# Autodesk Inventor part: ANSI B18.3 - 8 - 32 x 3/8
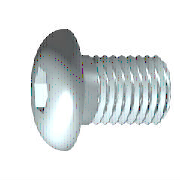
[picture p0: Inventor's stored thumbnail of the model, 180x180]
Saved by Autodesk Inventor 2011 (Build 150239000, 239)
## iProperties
IsCustomPart: 0
Created: 2008-02
Part Number: ANSI B18.3 - 8 - 32 x 3/8
Material: Steel, Mild
Description: Hexagon Socket Button Head Cap Screw
Document SubType Name: Modeling
Standard: ANSI B18.3
Standard Revision: 2003
Standards Organization: ANSI
Language: en-US
Size Designation: 8 - 32 x 3/8
Categories: <MemberInstance><Categories><Category DisplayName="Fasteners" InternalName="e4da775c-781d-43d5-af7c-5136215cf5a6" Mnemonic="FSTN"><Category DisplayName="Bolts"
Density: 1 g/cm^3
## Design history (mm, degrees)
body "Solid1"
workplane "Work Plane1"
fillet "Fillet2" dims "d30" = 0.1 (= R)
revolve "Body" stored, may be unused: angle "d10" = 90 deg
sketch "Sketch2"
  geometry: L1 (0, -5.547)-(0, 5.547) reference; L2 (-5.547, 0)-(5.547, 0) reference; L3 (1.378, 0)-(0.689, -1.194); L4 (0.689, -1.194)-(-0.689, -1.194); L5 (-0.689, -1.194)-(-1.378, 0); L6 (-1.378, 0)-(-0.689, 1.194); L7 (-0.689, 1.194)-(0.689, 1.194); L8 (0.689, 1.194)-(1.378, 0); 2 further points
  constraints: 12 end point, 1 coincident, 1 horizontal alignment, 1 point on line, 12 other
extrude "Slot" join sketch "Sketch2" stored distance "d11" = 10; taper "d12" = 0 deg
fillet "Fillet1" dims "d17" = 1.9558 (= RR)
feature "Thread" dims "d13" = 7.93476 (= GEL), "d14" = 0
chamfer "Chamfer1" distance "d15" = 0.48692 (= -0.5 x SPD + 0.5 x GD); stored, may be unused: second distance "d16" = 0.48692 (= GUL), angle "d27" = 45 deg
sketch "Sketch1"
  geometry: L1 (-0.093, 0)-(9.525, 0); L2 (9.525, 0)-(9.525, 2.083); L3 (9.525, 2.083)-(1.59, 2.083); L4 (1.59, 2.083)-(0, 2.083); L5 (0, 2.083)-(0, 2.083); L6 (0, 2.083)-(0, 3.962); L7 (0, 3.962)-(-2.21, 3.962); L8 (-2.21, 3.962)-(-2.21, 1.378); L9 (-2.21, 1.378)-(-0.889, 1.378); L10 (-0.889, 1.378)-(-0.093, 0); L11 (-4.557, 0)-(11.872, 0) reference; L12 (0, -0.792)-(0, 4.755) reference; L13 (1.59, 2.083)-(0, 2.083)
  constraints: 22 end point, 6 parallel, 2 collinear, 2 perpendicular, 1 horizontal, 1 point on line
  dimensions: "d1" = 7.93476 distance from line of L3.end L2 (= GEL); "d2" = 1.59014 distance of L4.end L3.end (computed from GAL); "d3" = 2.2098 distance between parallel lines of L8 L6 (= KOH); "d4" = 1.3208 distance of L8.end L9.end (= INTI); "d5" = 60 deg angle of L10 L1; "d6" = 4.1656 diameter of L3 L1 (= GD); "d7" = 4.1656 diameter of L5 L1 (= BDM); "d8" = 2.75696 diameter of L9 L1 (= 1.1547 x SW); "d9" = 7.9248 diameter of L7 L1 (= KOD); "d26" = 9.525 distance between parallel lines of L12 L2 (= NLG)
other parameters: "GD" = 4.1656 (= NND) [user parameter; used in 2 equation terms], "NLG" = 9.525 [user parameter; used in 1 equation term], "GEL" = 7.93476 [user parameter; used in 2 equation terms], "KOD" = 7.9248 [user parameter; used in 1 equation term], "KOH" = 2.2098 [user parameter; used in 1 equation term], "INTI" = 1.3208 [user parameter; used in 1 equation term], "GAL" = 1.59004 [user parameter; used in 1 equation term], "GUL" = 0.48692 [user parameter; used in 1 equation term], "BDM" = 4.1656 (= NND) [user parameter; used in 1 equation term], "SW" = 2.3876 [user parameter; used in 1 equation term], "RR" = 1.9558 [user parameter; used in 1 equation term], "SPD" = 3.19176 [user parameter; used in 2 equation terms], "d19" = 0, "d28" = 0, "d29" = 0, "R" = 0.1 [user parameter; used in 1 equation term], "TOA" = 30 deg [user parameter], "GD1" = 3.19176 (= SPD) [user parameter], "THREADDIA" = 4.1656 [user parameter], "PTC" = 0.79375 (computed from TPU) [user parameter], "KOH1" = 0.381 [user parameter], "NND" = 4.1656 [user parameter; used in 2 equation terms], "E0" = 2.75768 [user parameter]
